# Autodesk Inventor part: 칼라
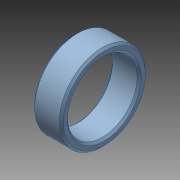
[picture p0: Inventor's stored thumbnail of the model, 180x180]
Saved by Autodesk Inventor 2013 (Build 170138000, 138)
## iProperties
Created: 2024-01
Part Number: 칼라
Material: 강철, 합금
Document SubType Name: Modeling
Designer: mdu-01
Density: 1 g/cm^3
Author: mdu-01
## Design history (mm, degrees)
sketch "스케치1"
  geometry: L1 (-3.5, 0)-(3.5, 0); L2 (-3, 8.5)-(3, 8.5); L3 (3.5, 9)-(3.5, 10); L4 (3, 10.5)-(-3, 10.5); L5 (-3.5, 10)-(-3.5, 9); L6 (-3, 10.5)-(-3.5, 10); L7 (-3, 8.5)-(-3.5, 9); L8 (3, 8.5)-(3.5, 9); L9 (3.5, 10)-(3, 10.5); 6 further points
  constraints: 18 end point, 10 point on line, 2 horizontal, 2 parallel, 1 coincident, 1 midpoint, 1 perpendicular
  dimensions: "d0" = 7 distance of L1.start L1.end; "d1" = 17 diameter of L2 L1; "d2" = 2 distance between parallel lines of L4 L2; "d3" = 0.5 distance of L4.end point (-3.5, 10.5); "d4" = 0.5 distance of L5.start point (-3.5, 10.5) (= d3); "d5" = 0.5 distance of L2.start point (-3.5, 8.5) (= d3); "d6" = 0.5 distance of L5.end point (-3.5, 8.5) (= d5); "d7" = 0.5 distance of L2.end point (3.5, 8.5) (= d3); "d8" = 0.5 distance of L3.start point (3.5, 8.5) (= d7); "d9" = 0.5 distance of L3.end point (3.5, 10.5) (= d3); "d10" = 0.5 distance of L4.start point (3.5, 10.5) (= d9)
revolve "회전1" sketch "스케치1" stored, may be unused: angle "d11" = 90 deg
node "솔리드1"
